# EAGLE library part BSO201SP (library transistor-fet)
OptiMOS(R)-P Small-Signal-Transistor P-Channel, Enhancement mode, Super Logic Level (2.5 V rated) RDS(on) 8mOhm, ID -14.9 a Source: http://www.infineon.com/upload/Document/cmc_upload/documents/011/3655/BSO201SP_211201.pdf
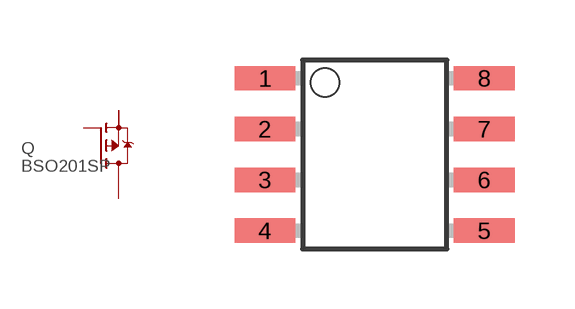
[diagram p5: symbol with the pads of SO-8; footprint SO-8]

Designator prefix Q

## BSO201SP  [SO-8]
1  S  pas
2  S  pas
3  S  pas
4  G  pas
5  D  pas
6  D  pas
7  D  pas
8  D  pas

## Footprint SO-8 (pad centres in mm)
SO 8 small outline
smd 1.524 x 0.61: 1 -2.743,1.905; 2 -2.743,0.635; 3 -2.743,-0.635; 4 -2.743,-1.905; 5 2.743,-1.905; 6 2.743,-0.635; 7 2.743,0.635; 8 2.743,1.905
